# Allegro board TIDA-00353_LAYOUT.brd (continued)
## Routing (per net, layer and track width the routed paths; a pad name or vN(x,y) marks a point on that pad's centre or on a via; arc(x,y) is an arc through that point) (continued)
FMC_ADC_DEVCLK-: length 78.6
  L3_POWER w0.203: v1(119.61,87.25) 119.75,87.25 119.9,87.39 119.9,87.57 119.79,87.68 106.02,87.68 v1(105.92,87.58)
  BOTTOM w0.203: FMC.D9 v1(119.61,87.25) ; v1(105.92,87.58) 105.82,87.68 105.26,87.68 89.13,71.55 68.31,71.55 64.17,67.42 64.17,64.17 61.17,61.17 61.17,56.13 R77.1
FMC_ADC_SYSREF+: length 79.7
  L3_POWER w0.203: v1(119.61,84.71) 119.18,84.28 106.02,84.28 v1(105.92,84.38)
  BOTTOM w0.203: v1(105.92,84.38) 105.82,84.28 103.94,84.28 99.2,79.54 99.2,78.26 99.77,77.69 102.34,77.69 102.54,77.5 102.54,76.6 102.34,76.4 98.15,76.4 89.02,67.27 69.08,67.27 63.77,61.96 63.77,56.85 R83.1 ; FMC.D11 v1(119.61,84.71)
FMC_ADC_SYSREF-: length 79.7
  L3_POWER w0.203: v1(105.92,83.77) 106.02,83.87 119.75,83.87 119.9,83.73 119.9,83.54 119.79,83.44 v1(119.61,83.44)
  BOTTOM w0.203: FMC.D12 v1(119.61,83.44) ; v1(105.92,83.77) 105.82,83.87 104.11,83.87 99.61,79.37 99.61,78.43 99.94,78.1 102.51,78.1 102.95,77.67 102.95,76.43 102.51,76 98.32,76 89.19,66.87 69.25,66.87 64.17,61.79 64.17,56.85 R82.1
FMC_FPGA_DEVCLKA+: length 86.3
  TOP w0.203: U13.51 86.15,49.82 86.11,49.85 86.11,50.62 87.11,51.63 87.11,56.31 104.52,73.71 124.76,73.71 130.31,79.26 130.31,91.41 126.64,95.07 120.3,95.07 119.72,94.49 119.72,93.7 v1(119.61,93.6)
  BOTTOM w0.203: FMC.D4 v1(119.61,93.6)
FMC_FPGA_DEVCLKA-: length 86.3
  TOP w0.203: v1(120.88,93.6) 120.88,93.37 120.68,93.17 120.3,93.17 120.12,93.34 120.12,94.32 120.47,94.67 126.47,94.67 129.9,91.24 129.9,79.43 124.59,74.12 104.35,74.12 86.71,56.48 86.71,51.79 85.7,50.79 85.7,49.85 85.67,49.82 U13.52
  BOTTOM w0.203: FMC.D5 v1(120.88,93.6)
FMC_FPGA_DEVCLKB+: length 86.3
  TOP w0.203: v1(115.8,92.33) 126.55,92.33 128.28,90.6 128.28,80.04 124.48,76.25 103.54,76.25 83.74,56.45 83.74,55.47 84.61,54.6 84.61,49.85 84.65,49.82 U13.54
  BOTTOM w0.203: FMC.G6 v1(115.8,92.33)
FMC_FPGA_DEVCLKB-: length 86.3
  TOP w0.203: v1(115.8,91.06) 115.8,91.57 116.16,91.92 126.38,91.92 127.87,90.43 127.87,80.21 124.31,76.66 103.37,76.66 83.33,56.62 83.33,55.31 84.21,54.43 84.21,49.85 84.17,49.82 U13.55
  BOTTOM w0.203: FMC.G7 v1(115.8,91.06)
FMC_FPGA_SYSREF+: length 86.3
  TOP w0.203: v1(117.07,87.25) 116.78,87.25 116.65,87.12 116.65,86.87 116.96,86.56 119.94,86.56 121.16,87.78 126.19,87.78 126.73,87.25 126.73,80.65 124.86,78.79 103.6,78.79 82.19,57.38 82.19,55.34 81.62,54.77 79.83,54.77 79.63,54.57 79.63,53.67 79.83,53.48 82.06,53.48 82.63,52.91 82.63,51.77 83.61,50.79 83.61,49.85 83.66,49.8 U13.56
  BOTTOM w0.203: FMC.G9 v1(117.07,87.25)
FMC_FPGA_SYSREF-: length 86.3
  TOP w0.203: U13.57 83.15,49.8 83.2,49.85 83.2,50.62 82.22,51.6 82.22,52.74 81.89,53.07 79.66,53.07 79.22,53.51 79.22,54.74 79.66,55.17 81.45,55.17 81.78,55.5 81.78,57.54 103.43,79.2 124.69,79.2 126.32,80.82 126.32,87.08 126.02,87.38 121.33,87.38 120.11,86.16 116.79,86.16 116.25,86.7 116.25,87.06 116.06,87.25 v1(115.8,87.25)
  BOTTOM w0.203: FMC.G10 v1(115.8,87.25)
INA+: length 27.3
  TOP w0.203: T2.1 30.16,86.35 31.23,85.28 37.28,85.28 47.66,74.89 49.71,74.89 R8.2
INA-: length 27.3
  TOP w0.203: T2.3 30.16,83.81 31.23,84.88 37.11,84.88 47.5,74.49 49.6,74.49 R9.2
INB+: length 27.3
  TOP w0.203: T6.3 30.16,57.04 31.23,58.11 37.28,58.11 47.66,68.49 49.63,68.49 R21.2
INB-: length 27.3
  TOP w0.203: T6.1 30.16,59.58 31.23,58.51 37.11,58.51 47.5,68.9 49.66,68.9 R20.2
LMH_VINA:
  vias: v1(12.29,87.51)
LMH_VINB:
  vias: v1(12.29,55.88)
LMK_ADC_DEVCLK+: length 0.7
  BOTTOM w0.203: R74.1 C172.2
LMK_ADC_DEVCLK-: length 0.7
  BOTTOM w0.203: C173.2 R75.1
LMK_ADC_SYSREF+: length 0.7
  BOTTOM w0.203: R81.1 C170.2
LMK_ADC_SYSREF-: length 0.7
  BOTTOM w0.203: C171.2 R80.1
LMK_DIR: length 1.7
  BOTTOM w0.203: U16.7 54.69,19.78 55.42,19.05 R144.2
LMK_VCC1/5/6: length 5.3
  TOP w0.203: v2(78.38,44.46) 78.49,44.36 U13.10
  TOP w0.254: v1(88.38,42.86) U13.36 ; U13.33 88.35,41.36 v2(88.38,41.33)
  BOTTOM w0.381: v2(78.38,44.46) C131.1 C130.1 78.86,45.68 L20.1 ; v2(88.38,41.33) C132.1 ; v1(88.38,42.86) C133.1
LMK_VCC2: length 1.9
  TOP w0.203: U13.17 79.65,40.2 v2(79.55,40.09)
  BOTTOM w0.381: C141.1 v2(79.55,40.09)
  BOTTOM w0.559: L24.2 79.63,40.01 v2(79.55,40.09)
LMK_VCC3: length 2.1
  TOP w0.203: U13.21 81.65,40.2 v2(81.75,40.09)
  BOTTOM w0.381: C142.1 v2(81.75,40.09)
  BOTTOM w0.559: L25.2 81.18,39.52 v2(81.75,40.09)
LMK_VCC4: length 2.4
  TOP w0.254: v2(84.19,40.15) 84.17,40.17 U13.26
  BOTTOM w0.381: v2(84.19,40.15) C143.1
  BOTTOM w0.559: L26.2 84.43,40.39 v2(84.19,40.15)
LMK_VCC7: length 2
  TOP w0.254: U13.39 v1(88.38,44.36)
  BOTTOM w0.381: C136.1 v1(88.38,44.36) 89.21,44.36 L22.2
LMK_VCC8/10: length 9.3
  TOP w0.254: U13.47 v1(88.38,48.37) ; U13.42 v1(88.38,45.88)
  L4_POWER w0.559: v1(88.38,45.88) 89.08,46.58 89.08,47.66 v1(88.38,48.37)
  BOTTOM w0.381: C138.1 C140.1 v1(88.38,45.88) 89.21,45.88 L22.1 ; L21.1 88.38,49.51 v1(88.38,48.37) ; C139.1 v1(88.38,48.37) ; v1(88.38,48.37) 89.06,48.37 L23.1
LMK_VCC9: length 2
  TOP w0.203: v1(88.38,47.35) 88.35,47.38 U13.45
  BOTTOM w0.381: L23.2 89.06,47.35 v1(88.38,47.35) C137.1
LMK_VCC11: length 1.8
  TOP w0.254: v1(85.16,50.01) U13.53
  BOTTOM w0.381: C144.1 v1(85.16,50.01) 85.81,50.66 L27.2
LMK_VCC12: length 2.4
  TOP w0.254: U13.64 v2(79.65,50.09)
  BOTTOM w0.381: v2(79.65,50.09) C145.1
  BOTTOM w0.559: v2(79.65,50.09) 78.49,50.09 L28.2
OVRA/TRIGRDY: length 48.3
  TOP w0.381: v2(105.64,71.37) 116.08,71.37 116.44,71.02 116.44,66.29 v1(115.8,65.66)
  L4_POWER w0.381: v2(81.64,87.88) 83.16,86.36 90.66,86.36 v2(105.64,71.37)
  BOTTOM w0.381: FMC.G27 v1(115.8,65.66)
OVRB/TRIGGER: length 47.6
  TOP w0.381: v1(119.61,66.93) 118.98,66.29 118.98,65.38 118.62,65.02 105.47,65.02 v2(102.93,67.56)
  L4_POWER w0.381: v2(102.93,67.56) 87.3,83.19 v2(81.77,83.19)
  BOTTOM w0.381: FMC.D26 v1(119.61,66.93)
PG_C2M: length 13.9
  TOP w0.381: R60.1 108.51,100.2 116.69,100.2 117.58,99.31 118.98,99.31 v1(119.61,98.68)
  BOTTOM w0.381: FMC.D1 v1(119.61,98.68)
PG_M2C: length 10.6
  TOP w0.381: R61.1 116.44,99.31 v1(117.07,98.68)
  BOTTOM w0.381: FMC.F1 v1(117.07,98.68)
REFCLK+: length 5.8
  TOP w0.203: C166.2 83.02,35.71 80.87,33.55 T5.6
REFCLK-: length 5.8
  TOP w0.203: T5.4 85.95,33.55 83.79,35.71 C165.2
RESET_LMK_3P3: length 16.9
  TOP w0.203: v2(73.38,23.89) v2(73.38,22.62)
  BOTTOM w0.203: R153.1 R152.2 74.27,21.73 v2(73.38,22.62) ; v2(73.38,23.89) 73.38,32.91 R95.1
SA0+: length 53.9
  TOP w0.203: v1(124.69,96.14) 124.26,96.57 123.56,96.57 122.98,97.16 106.73,97.16 83.41,73.84 82.15,73.84 81.97,73.66 C101.1
  BOTTOM w0.203: FMC.A3 v1(124.69,96.14)
SA0-: length 53.9
  TOP w0.203: C100.1 81.97,74.42 82.15,74.24 83.24,74.24 106.56,97.56 123.14,97.56 123.73,96.98 124.26,96.98 v1(124.69,97.41)
  BOTTOM w0.203: FMC.A2 v1(124.69,97.41)
SA1+: length 47.9
  TOP w0.203: C103.1 81.97,71.37 82.15,71.55 83.79,71.55 102.46,90.22 120.45,90.22 v1(120.88,89.79)
  BOTTOM w0.203: FMC.C7 v1(120.88,89.79)
SA1-: length 47.9
  TOP w0.203: C102.1 81.97,72.14 82.15,71.96 83.62,71.96 102.29,90.63 120.45,90.63 v1(120.88,91.06)
  BOTTOM w0.203: FMC.C6 v1(120.88,91.06)
SA_0+: length 14.9
  TOP w0.203: C101.2 80.93,73.66 80.75,73.84 71.6,73.84 70.75,72.99 67.46,72.99 67.42,72.94 U12.38
SA_0-: length 14.9
  TOP w0.203: U12.39 67.42,73.44 67.46,73.4 70.58,73.4 71.43,74.24 80.7,74.24 80.88,74.42 C100.2
SA_1+: length 14.8
  TOP w0.203: U12.36 67.42,71.94 67.46,71.99 74.23,71.99 74.67,71.55 80.83,71.55 81.01,71.37 C103.2
SA_1-: length 14.8
  TOP w0.203: U12.37 67.42,72.44 67.46,72.4 74.39,72.4 74.83,71.96 80.88,71.96 81.06,72.14 C102.2
SB0+: length 51.5
  TOP w0.203: v1(124.69,84.71) 124.26,85.14 102.71,85.14 84.55,66.98 82.15,66.98 81.97,66.8 C107.1
  BOTTOM w0.203: FMC.A11 v1(124.69,84.71)
SB0-: length 51.5
  TOP w0.203: C106.1 81.97,67.56 82.15,67.39 84.38,67.39 102.54,85.55 124.26,85.55 v1(124.69,85.98)
  BOTTOM w0.203: FMC.A10 v1(124.69,85.98)
SB1+: length 52.7
  TOP w0.203: C105.1 82.1,69.09 82.28,69.27 84.17,69.27 103.86,88.95 122.5,88.95 123.77,90.22 124.26,90.22 v1(124.69,89.79)
  BOTTOM w0.203: FMC.A7 v1(124.69,89.79)
SB1-: length 52.7
  TOP w0.203: C104.1 82.1,69.85 82.28,69.67 84,69.67 103.69,89.36 122.33,89.36 123.6,90.63 124.26,90.63 v1(124.69,91.06)
  BOTTOM w0.203: FMC.A6 v1(124.69,91.06)
SB_0+: length 15.8
  TOP w0.203: U12.32 67.42,69.94 67.46,69.99 71.72,69.99 74.73,66.98 80.83,66.98 81.01,66.8 C107.2
SB_0-: length 15.8
  TOP w0.203: C106.2 81.01,67.56 80.83,67.39 74.9,67.39 71.89,70.4 67.46,70.4 67.42,70.44 U12.33
SB_1+: length 15.3
  TOP w0.203: U12.34 67.42,70.94 67.46,70.99 72.58,70.99 74.31,69.27 80.75,69.27 80.93,69.09 C105.2
SB_1-: length 15.3
  TOP w0.203: U12.35 67.42,71.44 67.46,71.4 72.75,71.4 74.48,69.67 80.7,69.67 80.88,69.85 C104.2
SCLK_ADC_3P0: length 31.7
  TOP w0.203: v2(61.19,93.47) 62.04,92.62 62.04,80.43 v2(61.63,80.01) ; U12.53 61.22,76.68 v1(61.19,76.71)
  BOTTOM w0.203: R134.2 v2(61.19,93.47) J3.1 R65.2 ; v2(61.63,80.01) 61.63,77.14 v1(61.19,76.71)
SCLK_ADC_LMH_LMK: length 44.3
  TOP w0.203: v2(28.35,24.77) 37.9,24.77 38.41,24.26 40.28,24.26 40.79,24.77 v2(45.97,24.77) v2(45.97,28.83)
  BOTTOM w0.203: v2(45.97,24.77) 45.97,22.91 46.5,22.38 U16.14 ; R126.2 v2(28.35,24.77) 22.63,24.77 21.13,26.27 U15.14 ; U14.14 v2(45.97,28.83)
SCLK_LMH_3P3: length 40.9
  L4_POWER w0.203: J1.1 14.16,50.72 8.86,56.02 8.86,69.02 10.08,70.25 v2(10.15,70.25)
  BOTTOM w0.203: R138.2 19.24,41.28 J1.1
  BOTTOM w0.254: U3.2 10.35,70.44 v2(10.15,70.25)
SCLK_LMK_3P3: length 47.8
  TOP w0.203: U13.19 80.66,39.41 78.36,37.11 78.36,22.13 76.95,20.72 v2(75.54,20.72)
  BOTTOM w0.203: R150.1 R151.1 v2(75.54,20.72) 75.54,21.89 74.18,23.26 61.36,23.26 J2.1 58.02,24.27 R141.2
SDI_ADC_3P0: length 28
  TOP w0.203: v2(63.23,90.42) 64.75,88.9 v2(64.75,80.01) ; U12.47 64.22,76.8 v1(64.17,76.86)
  BOTTOM w0.203: R136.2 v2(63.23,90.42) J3.3 R63.1 ; v1(64.17,76.86) 64.37,77.06 64.37,79.63 v2(64.75,80.01)
SDI_ADC_LMH: length 37.9
  TOP w0.203: v2(31.41,25.65) v2(31.41,27.53)
  BOTTOM w0.203: U15.12 22.43,29.11 24,27.53 v2(31.41,27.53) 34.95,27.53 37.01,25.48 37.01,24.54 37.74,23.8 41.45,23.8 45.19,27.53 U14.12 ; v2(31.41,25.65) v1(31.41,21.93)
SDI_LMH_3P3: length 44.6
  L4_POWER w0.203: v2(10.97,69.76) 10.08,68.88 10.08,64.16 12.85,61.39 12.85,53.93 14.79,51.99 19.87,51.99 20.51,51.35 20.51,50.08 21.14,49.45 23.05,49.45 J1.3
  BOTTOM w0.203: R140.2 24.32,41.28 J1.3
  BOTTOM w0.254: U3.1 11.15,69.94 v2(10.97,69.76)
SDIO_LMK: length 14.2
  TOP w0.203: v1(34.43,21.93) 34.43,21.65 35,21.08 v2(46.79,21.08)
  BOTTOM w0.203: U16.12 v2(46.79,21.08)
SDIO_LMK_3P3: length 48.9
  TOP w0.203: U13.20 81.15,39.13 79,36.99 79,21.85 77.23,20.08 v2(70.71,20.08) v2(67.03,20.08)
  BOTTOM w0.203: J2.3 58.02,19.19 R143.2 ; J2.3 61.23,20.08 v2(67.03,20.08) ; J2.3 J2.4 ; v2(70.71,20.08) R149.1 R148.1
SDO_ADC: length 25
  TOP w0.203: v2(33.67,25.65) v2(33.67,26.88)
  BOTTOM w0.203: v2(33.67,26.88) 34.75,26.88 36.25,25.39 36.25,23.47 38.2,21.51 40.08,21.51 42.91,24.34 42.91,24.37 45.42,26.88 U14.11 ; v2(33.67,25.65) v1(33.67,21.93)
SDO_ADC_3P0: length 25.3
  TOP w0.203: U12.48 v1(63.72,76.44) ; v2(63.35,88.9) v2(63.35,80.01)
  BOTTOM w0.203: v1(63.72,76.44) 63.35,76.81 v2(63.35,80.01) ; R64.1 J3.4 64.24,88.9 v2(63.35,88.9) R137.2
SYNC_LMK_3P3: length 25.6
  TOP w0.203: v2(76.71,35.92) 76.71,22.31 76.39,21.99 v2(68.94,21.99)
  BOTTOM w0.203: R155.1 R156.2 v2(68.94,21.99)
SYNCB+: length 75
  TOP w0.203: U12.27 65.72,67.31 65.77,67.26 65.77,66.67 66.5,65.94 66.5,59.27 70.17,55.6 77.92,55.6 102.38,80.06 116.05,80.06 116.64,80.65 116.64,83.01 117,83.36 v1(117.07,83.44)
  BOTTOM w0.203: FMC.G12 v1(117.07,83.44)
SYNCB-: length 75
  TOP w0.203: U12.28 66.22,67.31 66.17,67.26 66.17,66.84 66.91,66.11 66.91,59.44 70.34,56.01 77.75,56.01 102.21,80.47 115.88,80.47 116.24,80.82 116.24,82.83 116.11,82.96 115.27,82.96 115.13,83.1 115.13,83.27 115.3,83.44 v1(115.8,83.44)
  BOTTOM w0.203: FMC.G13 v1(115.8,83.44)
SYSREF+: length 4.2
  TOP w0.203: U12.23 63.72,67.28 63.77,67.24 63.77,64.15 63.6,63.98 C110.2
SYSREF-: length 4.2
  TOP w0.203: U12.24 64.22,67.28 64.17,67.24 64.17,64.15 64.35,63.98 C111.2
SYSREF_VIN+: length 9.1
  TOP w0.203: C110.1 63.6,62.5 R50.2 63.77,62.33 63.77,55.17 v1(63.46,54.86)
  BOTTOM w0.203: v1(63.46,54.86) R83.2
SYSREF_VIN-: length 9.1
  TOP w0.203: C111.1 64.35,62.5 R50.1 64.17,62.33 64.17,55.17 v1(64.48,54.86)
  BOTTOM w0.203: v1(64.48,54.86) R82.2
V_VCXO3.3: length 83.9
  TOP w0.559: V_VCXO3P3.1 Z13.3 v2(102.44,28.97) ; v2(97.03,57.62) C169.1 98.68,57.62 ; 98.68,57.62 100.67,57.62 ; 98.68,57.62 v2(98.68,58.15) v2(100.67,58.15) 100.67,57.62 ; 98.68,57.62 v2(98.68,57.09) v2(100.67,57.09) 100.67,57.62
  TOP w0.762: v2(100.51,51.32) v2(100.51,52.64)
  L3_POWER w0.559: 100.67,57.62 v2(100.67,57.09) v2(98.68,57.09) 98.68,57.62 ; 100.67,57.62 98.68,57.62 ; 100.67,57.62 v2(100.67,58.15) v2(98.68,58.15) 98.68,57.62 ; 98.68,57.62 v2(97.03,57.62)
  L3_POWER w1.27: V_VCXO3P3.1 104.86,52.44 100.67,56.63 100.67,57.62
  BOTTOM w0.762: 98.68,53.17 98.68,52.64 v2(100.51,52.64) ; 98.68,53.17 98.68,53.71 100.67,53.71 100.67,52.64 v2(100.51,52.64) ; 98.68,53.17 100.51,53.17 ; 100.67,57.62 v2(100.67,57.09) v2(98.68,57.09) v2(98.68,58.15) v2(100.67,58.15) 100.67,57.62 ; 100.67,57.62 100.51,57.62 ; v2(100.51,52.64) v2(100.51,51.32) Y3.6 ; v2(100.51,52.64) 100.51,53.17 ; 100.51,57.62 100.51,53.17 ; 100.51,57.62 v2(97.03,57.62)
  BOTTOM w1.27: Z13.3 V_VCXO3P3.1
  vias: v2(104.35,29.33) v2(104.35,28.62) v2(105.36,29.33) v2(105.36,28.62)
V_XO3.3: length 36.3
  TOP w0.559: 97.07,35.74 v2(97.47,35.74) v2(97.47,33.67) ; 97.07,35.74 Y1.6 ; 97.07,35.74 v2(96.66,35.74) v2(96.66,33.67) ; v2(97.47,33.67) Y1.6 ; v2(97.47,33.67) v2(97.47,31.6) 97.07,31.6 ; Y1.6 97.07,31.6 ; Y1.6 v2(96.66,33.67) ; v2(93.64,17.85) Z12.3 ; v2(96.66,33.67) v2(96.66,31.6) 97.07,31.6
  TOP w1.016: v2(96.66,31.6) 96.05,30.99 v1(96.05,22.9) V_XO3P3.1 Z12.3
  BOTTOM w0.381: v1(96.05,22.9) V_XO3P3.1
  BOTTOM w1.27: Z12.3 V_XO3P3.1
  vias: v2(95.54,18.2) v2(95.54,17.5) v2(96.56,18.2) v2(96.56,17.5)
VA1.2: length 194.7
  TOP w0.203: v2(58.6,54.04) 57.82,53.26 SYSREF_SW.1 ; C85.1 63.1,65.76 62.72,66.14 U12.21
  TOP w0.305: U12.30 67.71,68.94 68.05,68.61 C93.1 ; C74.2 56.75,71.25 56.95,71.44 U12.8 ; C65.1 62.87,77.16 62.72,77.01 U12.50
  TOP w0.381: C65.1 62.87,77.83 v1(62.84,77.85) C64.1 v1(62.84,79.12) ; C74.2 56.39,70.97 v1(55.99,71.37) ; v1(68.97,68.58) 68.48,68.58 C93.1 ; C85.1 v1(63.15,65.34)
  TOP w0.406: v1(68.97,68.58) 69.16,68.58 v1(69.53,68.95) C92.1
  TOP w0.559: 53.79,100.85 C207.1 ; v2(56.53,100.49) v2(56.53,101.2) v2(55.52,101.2) v2(54.5,101.2) v2(54.5,100.49) v2(55.52,100.49) v2(56.53,100.49)
  TOP w1.27: VA1P2.1 52.04,97.55 C206.1 Z4.3
  L3_POWER w0.203: v2(58.6,54.04) 63.94,59.38 63.94,64.55 v1(63.15,65.34)
  L4_POWER w0.635: v1(68.97,68.58) 69.16,68.58 v1(69.53,68.95) 69.98,69.39 69.98,73.33 67.67,75.64 67.67,83.31 69.39,85.03 69.39,101.22 65.86,104.75 58.8,104.75 58.06,104.01 58.06,102.01 57.26,101.2 v2(56.53,101.2) v2(56.53,100.49) ; v2(54.5,101.2) v2(54.5,100.49) 54.5,98.51 54.84,98.17 54.84,87.99 58.53,84.3 58.53,76.96 59.29,76.2 59.29,68.5 59.97,67.82 62.08,67.82 62.46,67.44 62.46,66.03 v1(63.15,65.34) ; v1(62.84,77.85) v1(62.84,79.12) 62.84,79.37 62.46,79.75 62.46,83.41 57.79,88.09 57.79,97.5 55.52,99.77 v2(55.52,100.49) v2(55.52,101.2) ; VA1P2.1 52.05,95.89 53.07,94.87 53.07,85.34 51.29,83.57 51.29,76.65 52.78,75.16 52.78,75.13 52.92,74.99 52.92,74.39 52.78,74.24 52.78,74.19 55.6,71.37 v1(55.99,71.37)
  BOTTOM w0.381: C76.2 56.6,71.37 v1(55.99,71.37) 56.14,71.53 C75.2 ; C91.1 v1(68.97,68.58) ; v1(63.15,65.34) 62.86,65.63 C84.1
VA1.8: length 338.3
  TOP w0.203: U12.20 62.22,66.14 61.84,65.76 C80.1
  TOP w0.254: v1(59.72,65.56) 59.66,65.61 59.66,67.06 59.72,67.11 U12.15
  TOP w0.284: U12.56 59.72,77.32
  TOP w0.305: U12.29 67.45,68.44 67.69,68.2 67.69,67.82 v1(67.7,67.82) ; 59.72,77.32 C67.1 ; U12.7 56.94,71.94 56.75,72.14 C73.2 ; U12.51 62.22,77.31 C69.1
  TOP w0.33: C82.1 v1(59.72,65.56)
  TOP w0.381: C69.1 v1(62.18,77.88) 62.2,77.88 C68.1 62.21,78.99 v1(62.08,79.12) ; C90.2 v1(68.33,67.82) v1(67.7,67.82) ; v1(59.42,79.12) C66.1 59.42,77.88 v1(59.47,77.83) 59.7,77.6 C67.1 ; C80.1 v1(61.8,65.34) ; C73.2 56.72,72.39 56.22,72.39 v1(55.99,72.16)
  TOP w0.762: Z7.3 C217.1
  TOP w1.27: VA1P8.1 Z7.3
  L3_POWER w0.635: 45.06,32 v2(44.68,32) v2(44.68,32.77) 45.06,32.77 ; 45.06,32 45.06,32.77 ; 45.06,32 v2(45.45,32) v2(45.45,32.77) ; v2(45.45,32.77) 45.45,35.38 46.51,36.45 46.51,38.33 50.65,42.47 50.65,66.05 55.17,70.56 55.17,71.73 55.6,72.16 v1(55.99,72.16) ; v2(45.45,32.77) 45.06,32.77 ; v1(59.42,79.12) 59.42,77.88 v1(59.47,77.83) 59.47,76.89 57.38,74.8 57.38,69.16 58.43,68.12 58.43,64.34 57.73,63.65 57.73,57.3 51.99,51.56 51.99,40.08 50.91,38.99 50.91,35.69 48.37,33.15 VA1P8.1 49.63,32.38 52.18,34.93 52.18,38.71 53.34,39.88 53.34,50.47 58.13,55.26 58.13,55.47 58.56,55.89 58.81,55.89 60.93,58.01 60.93,67.16 60.03,68.06 59.8,68.06 58.83,69.03 58.83,69.26 58.83,74.6 59.95,75.72 61.96,75.72 62.51,76.28 62.51,76.89 62.18,77.22 v1(62.18,77.88) 62.08,77.98 v1(62.08,79.12)
  L4_POWER w0.635: VA1P8.1 48.37,33.45 46.23,35.59 46.23,40.28 46.53,40.59 46.53,50.24 48.42,52.12 51.97,52.12 62.48,62.64 64.52,62.64 68.33,66.45 v1(68.33,67.82) v1(67.7,67.82) ; v1(61.8,65.34) 61.8,65.18 49.99,53.37 42.47,53.37 41.13,52.02 41.13,36.21 44.57,32.77 v2(44.68,32.77) v2(45.45,32.77) ; v2(45.45,32) v2(44.68,32) 43.62,30.94 41.33,30.94 39.81,32.46 39.81,52.45 42.47,55.12 49.63,55.12 57.51,62.99 57.51,63.35 v1(59.72,65.56)
  BOTTOM w0.203: C89.2 67.54,67.82 v1(67.7,67.82) v1(68.33,67.82)
  BOTTOM w0.33: C79.1 59.84,65.43 v1(59.72,65.56)
  BOTTOM w0.381: C72.2 56.57,72.39 56.22,72.39 v1(55.99,72.16) ; C81.1 61.52,65.63 v1(61.8,65.34)
  BOTTOM w1.27: Z7.3 VA1P8.1
VA3.0: length 202.8
  TOP w0.295: U12.42 67.46,74.94
  TOP w0.305: U12.2 58.25,74.44 58.09,74.6 57.05,74.6 56.75,74.3 C71.1 ; C94.2 67.7,75.18 67.46,74.94 ; C77.2 56.65,68.96 56.77,68.83 58.14,68.83 58.25,68.94 U12.13
  TOP w0.381: C77.2 56.14,69.34 v1(55.89,69.09) ; v1(55.99,74.3) 56.24,74.04 C71.1 ; C94.2 v1(68.71,75.79)
  TOP w0.762: C226.1 Z9.3
  TOP w1.27: Z9.3 VA3.0.1
  L4_POWER w0.635: 72.37,76.2 79.83,83.66 79.83,92.2 84.59,96.96 84.59,100.71 83.85,101.44 v2(83.29,101.44) ; 72.37,76.2 74.22,74.35 74.22,66.04 67.59,59.41 65.43,59.41 62.43,56.41 58.65,56.41 55.8,53.57 55.8,52.25 53.94,50.38 49.2,50.38 48.78,49.96 v2(48.56,49.96) v2(47.85,49.96) ; 72.37,76.2 69.12,76.2 v1(68.71,75.79) ; v1(55.89,69.09) 53.59,69.09 52.92,68.42 52.92,68.39 52.5,67.97 52.47,67.97 51.61,67.11 51.61,65.68 47.65,61.72 35.28,61.72 29.11,55.55 29.11,50.85 26.72,48.46 26.72,43.79 27.89,42.62 29.27,42.62 v2(30.49,41.4) ; v1(55.99,74.3) 57.13,73.15 57.13,69.04 56.38,68.29 55.74,68.29 55.31,67.86 55.31,66.78 48.55,60.01 37.25,60.01 34.67,57.43 34.67,46.81 33.15,45.29 v2(33.15,41.35) v2(32.44,41.35)
  BOTTOM w0.381: C70.1 56.24,74.04 v1(55.99,74.3) ; v1(68.71,75.79) 68.56,75.64 C95.2
  BOTTOM w0.406: C78.2 56.14,69.34 v1(55.89,69.09)
  BOTTOM w1.27: Z9.3 VA3.0.1
  vias: v2(31.2,41.4) v2(32.83,40.69) v2(44.68,43.31) v2(44.68,42.44) v2(45.54,43.3) v2(45.53,42.44)
VA3.0_LED: length 137.5
  TOP w0.762: C228.1 Z14.3
  TOP w1.27: Z14.3 VA3.0_LED.1
  L4_POWER w0.508: JP1.1 43.83,27.84 45.18,29.19 45.18,29.49 46.84,31.14 ; 46.84,31.14 47.78,30.2 48.82,30.2 v2(54.11,24.92) ; 46.84,31.14 46.58,31.39 46.58,33.27 43.92,35.94 43.92,43.97 44.68,44.73 v2(44.68,47.24)
  L4_POWER w0.635: v2(101.83,64.52) 101.38,64.97 76.28,64.97 ; 76.28,64.97 76.28,76.05 80.62,80.39 v2(87.86,80.39) ; 76.28,64.97 76.28,63.59 74.49,61.8 74.49,60.5 68.22,54.23 66.76,54.23 61.55,49.02 60.25,49.02 59.33,48.11 48.64,48.11 VA3.0_LED.1
  BOTTOM w0.203: v2(54.11,24.92) U14.8
  BOTTOM w0.381: v2(87.86,85.09) v2(87.86,80.39)
  BOTTOM w1.27: Z14.3 VA3.0_LED.1
  vias: v2(44.68,48.13) v2(45.57,48.13) v2(45.57,47.24)
VADJ: length 75.7
  TOP w0.508: v2(105.14,99.31) R61.2 ; v1(119.61,49.15) v1(118.34,49.15) v1(117.07,49.15) v1(115.8,49.15) 113.16,46.51 v2(110.65,46.51) 107.55,46.51 106.41,47.65 R69.1
  BOTTOM w0.381: FMC.H40 v1(115.8,49.15) ; FMC.F40 v1(118.34,49.15) ; FMC.E39 v1(119.61,49.15) ; FMC.G39 v1(117.07,49.15)
  BOTTOM w0.635: v2(105.14,99.31) 110.65,93.8 v2(110.65,46.51)
VAMP: length 15.3
  BOTTOM w0.203: v2(15.17,68.04) 14.99,68.22 U3.27 ; U3.14 14.99,75.17 v2(15.17,75.35)
  BOTTOM w0.381: v2(15.17,67.15) C24.2 ; C26.2 v2(15.17,76.24) ; v2(15.17,68.04) C25.1 ; v2(15.17,75.35) C27.1
  BOTTOM w0.406: R30.2 v1(8.53,69.83) ; 15.41,76.24 15.41,75.35 ; C24.2 C25.1 ; C26.2 C27.1 ; v2(15.17,67.15) v2(15.17,68.04) ; R33.2 v1(8.53,73.56) ; v2(15.17,76.24) v2(15.17,75.35) ; 15.41,67.15 15.41,68.04
  BOTTOM w0.762: v2(7.65,49.7) 10.22,49.7 Z17.3 v2(10.16,51.48)
  vias: v2(9.58,49.98) v2(9.58,49.28) v2(10.74,49.98) v2(10.74,49.28) v2(10.85,68.48)
VD1.2: length 78.9
  TOP w0.203: 62.24,100.85 62.24,101.02 C209.1
  TOP w0.254: U12.26 65.22,67.11 65.36,66.97 65.36,65.87 65.25,65.76 65.25,65.48
  TOP w0.305: C62.1 65.36,77.28 65.22,77.14 U12.45
  TOP w0.33: C88.1 65.25,65.48 v1(65.38,65.35)
  TOP w0.381: C62.1 65.64,77.62 v1(65.64,77.85) C61.1 v1(65.64,79.12)
  TOP w1.27: Z6.3 C208.1 59.66,97.67 VD1P2.1
  L4_POWER w0.635: v2(63.14,101.2) v2(63.14,100.49) 62.2,99.56 62.2,87.18 64.88,84.51 64.88,83.69 65.64,82.93 v1(65.64,79.12) v1(65.64,77.85) ; v1(65.38,65.35) 65.64,65.61 65.64,67.41 66.71,68.48 66.71,85.62 65.41,86.92 65.41,99.24 v2(64.15,100.49) v2(64.15,101.2)
  BOTTOM w0.33: C87.1 v1(65.38,65.35) 65.38,65.36 C86.2
VIO_B_M2C: length 8.1
  TOP w0.508: R69.2 108.77,48.39 109.28,47.88 v1(111.99,47.88) v1(113.26,49.15)
  BOTTOM w0.381: FMC.K40 v1(111.99,47.88) ; FMC.J39 v1(113.26,49.15)
VLMK3.3: length 119
  TOP w0.559: v2(57.76,45.87) v2(57.12,45.87) v2(56.49,45.87) 54.48,43.87 54.48,38.81 ; 18.88,42.57 35.43,42.57 39.19,38.81 54.48,38.81 ; 18.88,42.57 18.88,44.38 23.24,48.74 v1(25.84,48.74) ; 18.88,42.57 v1(18.88,31.36) ; 54.48,38.81 54.48,30.17 v1(48.94,24.63) ; v2(83.06,15.87) Z11.3 VLMK3P3.1
  L4_POWER w0.559: v2(71.91,45.87) v2(71.27,45.87) v2(70.64,45.87) v2(57.76,45.87) v2(57.12,45.87) v2(56.49,45.87)
  BOTTOM w0.203: v1(48.94,24.63) 48.94,24.05 48.57,23.68 U16.16 ; U15.16 v1(18.88,31.36)
  BOTTOM w0.381: C135.1 v2(76.64,48.79)
  BOTTOM w0.559: L28.1 78.36,48.69 L20.2
  BOTTOM w0.762: L21.2 v2(88.02,51.21) 87.76,51.21 v2(87.23,50.67) ; L28.1 v2(78.24,48.79) v2(76.64,48.79) ; v2(81.18,38) L24.1
  BOTTOM w1.27: Z11.3 VLMK3P3.1
  vias: v2(69.09,23.87) v2(75.7,23.87) v2(84.97,16.22) v2(84.97,15.51) v2(85.48,38.96) v2(85.98,16.22) v2(85.98,15.51)
VSPI1.8: length 52.9
  TOP w0.381: R123.2 v1(35.96,21.98) ; v2(30.59,20.43) 30.11,20.91 R122.2 R124.2
  TOP w0.559: Z3.3 v2(17.33,12.62)
  TOP w1.27: VSPI1.8.1 Z3.3
  L4_POWER w0.559: v1(20.26,30) 18.79,28.52 18.79,16.52 VSPI1.8.1 ; v2(42.22,21.98) v2(41.66,21.98) ; v2(42.22,21.98) v2(42.78,21.98) 45.47,21.98 v1(46.74,23.25) ; v2(42.22,21.98) 42.22,24.08 46.08,27.94 46.4,27.94 46.91,28.45 v2(46.91,29.42) ; v2(41.66,14.05) v2(42.22,14.05) v2(42.78,14.05) 49.18,14.05 JP2.1
  BOTTOM w0.203: v1(20.26,30) 20.48,30.21 U15.15 ; U16.15 46.95,23.03 v1(46.74,23.25) ; U14.15 46.98,29.48 v2(46.91,29.42)
  BOTTOM w0.381: C184.1 30.59,20.86 v2(30.59,20.43) U6.4
  BOTTOM w0.508: v2(46.91,29.42) 46.53,29.42 46.45,29.49 C190.2
  vias: v2(19.23,12.97) v2(19.23,12.26) v2(20.25,12.97) v2(20.25,12.26)
N17161280: length 19.6
  TOP w0.508: 33.72,46.6 C224.1 35.32,46.78 R170.2 ; 33.72,46.6 U10.5 ; 33.72,46.6 C223.1
  TOP w0.762: R179.1 Z14.1
  TOP w1.27: 40.28,44.93 Z9.1 ; 40.28,44.93 C223.1 ; 40.28,44.93 Z14.1
N17161345: length 4
  TOP w0.254: C224.2 35.32,48.05 R170.1 R171.1
  TOP w0.508: C224.2 U10.6
N17161357: length 1.2
  TOP w0.254: C222.1 U10.1
N17161563: length 64.3
  TOP w0.508: 100.49,13.02 U11.5 ; 100.49,13.02 C233.1 100.62,11.6 100.62,10.22 R177.2 ; 100.49,13.02 C234.1
  TOP w0.762: R180.1 Z12.1
  TOP w1.27: Z12.1 C234.1
  L4_POWER w0.559: 105.36,24.15 v2(105.36,23.79) v2(104.35,23.79) 104.35,24.15 ; 105.36,24.15 v2(105.36,24.5) v2(104.35,24.5) 104.35,24.15 ; 105.36,24.15 104.35,24.15 ; 95.54,13.02 v2(95.54,12.67) v2(96.56,12.67) v2(96.56,13.38) v2(95.54,13.38) 95.54,13.02 ; 95.54,13.02 Z12.1
  L4_POWER w1.27: Z12.1 99.58,13.02 100.08,12.52 105.19,12.52 106.48,13.82 106.48,22.52 105.36,23.64 105.36,24.15
  BOTTOM w0.559: 96.56,13.02 v2(96.56,13.38) v2(95.54,13.38) v2(95.54,12.67) v2(96.56,12.67) 96.56,13.02 ; 96.56,13.02 Z12.1 ; 105.36,24.15 v2(105.36,23.79) v2(104.35,23.79) 104.35,24.15 ; 105.36,24.15 104.35,24.15 ; 105.36,24.15 v2(105.36,24.5) v2(104.35,24.5) 104.35,24.15 ; 84.97,11.04 v2(84.97,11.39) v2(85.98,11.39) v2(85.98,10.69) v2(84.97,10.69) 84.97,11.04 ; 84.97,11.04 85.4,11.04
  BOTTOM w1.27: 85.4,11.04 91.3,11.04 93.29,13.02 Z12.1
N17161629: length 2.7
  TOP w0.203: R176.1 R175.2
  TOP w0.254: R175.2 U11.8
N17161669: length 4.1
  TOP w0.254: R178.1 R177.1 101.94,11.6 C233.2
  TOP w0.508: C233.2 U11.6
N17161679: length 1.2
  TOP w0.305: U11.1 v2(103.71,18.01)
N17161879: length 23.9
  TOP w0.508: 75.41,100.14 U8.5 ; 75.41,100.14 v2(75.41,98.72) ; 75.41,100.14 C204.1
  TOP w1.27: C204.1 73.11,100.14 71.12,102.13 68.99,102.13 65.45,105.67 Z6.1 Z4.1
N17161936: length 4.7
  TOP w0.406: U8.8 80.46,100.14 R235.2 81.5,100.15 C200.2 R161.2 R160.2
N17162041: length 11.7
  TOP w0.508: R166.2 35.7,33.7 C215.1 34.1,33.52 ; 34.1,33.52 U9.5 ; 34.1,33.52 C214.1
  TOP w1.27: Z7.1 38.84,32.38 38.3,31.85 C214.1
N17162051: length 4.8
  TOP w0.508: C210.2 R165.2 R164.2 ; C210.2 34.09,38.9 R236.2 ; C210.2 U9.8
N17162120: length 4
  TOP w0.254: C215.2 35.7,34.97 R166.1 R167.1
  TOP w0.508: U9.6 C215.2
N17162132: length 1.2
  TOP w0.254: U9.1 C213.1
N17162350: length 3
  TOP w0.254: v2(77.04,98.72) R162.1 R163.1
  TOP w0.508: U8.6 v2(77.04,98.72)
N17162360: length 1.2
  TOP w0.305: U8.1 C203.1
N17167261: length 1.7
  BOTTOM w0.203: LMKSPI.2 R147.2
N17167267: length 1.8
  BOTTOM w0.203: LMKSPI.4 70.71,16.08 R149.2
N17167273: length 1.7
  BOTTOM w0.203: R151.2 LMKSPI.8
N17204057: length 14.8
  BOTTOM w0.33: Y3.1 100.02,40.68 C162.1 88.69,38.21 R103.2
N17204061: length 2.6
  TOP w0.203: U13.32 87.17,39.74 C160.1 C161.1
  vias: v2(88.69,39.64)
N17204110: length 26.9
  TOP w0.33: REFCLK.1 79.12,3.87 80.87,5.62 T5.1
N17204122: length 1
  TOP w0.254: U13.12 v1(78.43,43.36)
  BOTTOM w0.381: C149.1 v1(78.43,43.36)
N17204150: length 2.3
  BOTTOM w0.203: Y1.4 91.99,35.24 v1(91.5,35.73)
N17204206: length 2.3
  TOP w0.203: U13.11 78.1,43.87 77.25,44.73 C148.1
N17204360: length 34.6
  TOP w0.33: R108.1 R107.2 89.65,6.04 91.82,3.87 EXTREF.1
N17204562: length 3.2
  TOP w0.203: C151.1 C150.1 89.12,47.86 U13.46
N17204592: length 1.4
  TOP w0.203: C150.2 R100.1
N17204632:
  vias: v1(94.92,46.23)
N17204638: length 1.7
  TOP w0.33: C158.2 R101.2 R102.1
N17204674: length 3.9
  BOTTOM w0.381: Y1.1 v1(97.07,23.79) R112.1
N17204744: length 1.8
  TOP w0.203: C152.1 89.29,46.82 88.14,46.82 88.09,46.87 U13.44
N17243114: length 85.7
  TOP w0.203: v1(109.4,53.59) 113.9,53.59 v1(114.53,52.96)
  BOTTOM w0.203: R65.1 74.4,93.22 105.69,93.22 109.4,89.51 v1(109.4,53.59) ; v1(114.53,52.96) FMC.H37
N17243121: length 87
  TOP w0.203: v1(108.59,51.05) 113.9,51.05 v1(114.53,50.42)
  BOTTOM w0.203: R66.1 73.26,91.82 105.92,91.82 108.59,89.15 v1(108.59,51.05)
  BOTTOM w0.381: FMC.H38 v1(114.53,50.42)
N17243521: length 83.2
  TOP w0.203: v1(115.8,54.23) 115.17,54.86 v1(107.78,54.86)
  BOTTOM w0.203: R63.2 72.24,90.3 106.28,90.3 107.78,88.8 v1(107.78,54.86) ; FMC.G36 v1(115.8,54.23)
N17243524: length 84.5
  TOP w0.203: v1(115.8,51.69) 115.17,52.32 v1(106.96,52.32)
  BOTTOM w0.203: v1(106.96,52.32) 106.96,88.44 106.51,88.9 71.1,88.9 R64.2 ; v1(115.8,51.69) FMC.G37
N17262131: length 21.5
  TOP w0.305: v1(67.8,74.55) 67.67,74.42 66.68,74.42 U12.41
  TOP w0.381: C96.1 68.18,74.42 68.05,74.55 v1(67.8,74.55)
  BOTTOM w0.381: C98.1 67.14,75.21 v1(67.8,74.55) 68.05,74.55 69.32,73.28 C97.2 74.4,73.28 75.04,73.91 80.6,73.91 81.77,75.08 BP2.5.1
N17267182: length 13
  TOP w0.203: v2(78.38,46.26) 78.49,46.36 U13.6 ; v2(75.7,35.92) v2(75.7,36.8)
  BOTTOM w0.203: v2(78.38,46.26) 77.78,45.66 77.78,38.89 v2(75.7,36.8) v2(75.7,35.92)
N17394464: length 2.1
  TOP w0.381: Q4.3 SYNC.2
  vias: v2(102.6,60.33)
N17403168: length 1.9
  TOP w0.381: OVRA/TRIGRDY.1 R58.1
N17405429: length 1.8
  TOP w0.381: OVRB/TRIGGER.1 R57.1
N17407540: length 26.4
  TOP w0.305: U12.44 65.72,76.59 66.53,77.39
  TOP w0.381: R53.1 79.61,87.88 76.65,84.92 67.84,84.92 66.78,83.86 66.78,77.65 66.53,77.39 ; R53.1 Q2.1 ; R53.1 R56.2
N17407548: length 22.8
  TOP w0.305: 67.54,77.52 66.22,76.2 U12.43
  TOP w0.381: R54.1 Q3.1 ; R54.1 68.69,83.19 67.54,82.04 67.54,77.52 ; R54.1 R55.2
N17461045: length 6
  TOP w0.203: STATUS_LD2.1 89.84,52.15 88.39,50.69 88.39,49.25 88.02,48.88 U13.48
N17467440: length 6.1
  TOP w0.33: C158.1 v1(90.49,46.23) ; C159.2 v1(90.49,41.74)
  BOTTOM w0.33: v1(90.49,46.23) v1(90.49,43.24) v1(90.49,41.74)
N17467450: length 1.8
  TOP w0.203: C153.1 89.29,46.41 88.14,46.41 88.09,46.36 U13.43
N17467802: length 1.8
  TOP w0.203: U13.35 88.09,42.37 88.14,42.32 89.29,42.32 C156.1
N17467807: length 1.8
  TOP w0.203: C157.1 89.29,41.92 88.14,41.92 88.09,41.87 U13.34
N17467978: length 1.8
  TOP w0.203: U13.38 88.09,43.87 88.14,43.82 89.29,43.82 C154.1
N17467983: length 1.8
  TOP w0.203: C155.1 89.29,43.42 88.14,43.42 88.09,43.36 U13.37
N17471425: length 19.1
  TOP w0.203: U13.31 86.66,40.37 86.29,40.01 86.29,35.99 87.76,34.52 87.76,24.07 STATUS_LD1.1
N17477944: length 12.2
  TOP w0.203: CLKIN_SEL1.1 75.37,50.93 79.66,50.93 80.46,50.13 81.91,50.13 82.16,49.88 U13.59
N17492975: length 15.2
  TOP w0.203: R94.2 v2(74.48,35.92) ; U13.5 78.49,46.87 v2(78.38,46.97)
  BOTTOM w0.203: R95.2 v2(74.48,35.92) 74.48,37.62 77.2,40.34 77.2,45.92 78.24,46.97 v2(78.38,46.97)
N17497915: length 7.5
  TOP w0.203: LMK_RESET.2 69.09,29.95 69.52,30.38 70.79,30.38 R94.1
N17498425: length 5.4
  TOP w0.203: R97.1 LMK_SYNC.2
N17498929: length 9.4
  TOP w0.381: Q4.1 R67.1 113.88,59.92 v1(114.53,60.58)
  BOTTOM w0.381: FMC.H31 v1(114.53,60.58)
N17500015: length 0.9
  BOTTOM w0.381: FMC.D31 v1(119.61,60.58)
N17500071: length 0.9
  BOTTOM w0.381: FMC.D30 v1(119.61,61.85)
N17502672: length 2.6
  TOP w0.254: U10.8 R168.2 R169.1
N17525558: length 11.6
  TOP w0.203: U13.58 82.64,50 81.97,50.67 80.7,50.67 79.91,51.46 CLKIN_SEL0.1
N17567551: length 17
  TOP w0.203: v2(52.85,54.3) 51.82,53.26 SYSREF_SW.2
  TOP w0.381: R51.2 v1(62.35,63.86)
  BOTTOM w0.203: v2(52.85,54.3) 52.85,56.33 R52.1 C113.2 v1(62.35,63.86)
N17588026: length 13.1
  BOTTOM w0.203: L1.1 R36.2 25.73,65.36 22.3,65.36 17.66,69.99 16.94,69.99 16.89,69.94 U3.24
N17588195: length 1.9
  BOTTOM w0.203: C21.2 13.3,61.08 12.47,60.26 T9.3
N17588197: length 1.9
  BOTTOM w0.203: T9.1 15.01,60.26 14.19,61.08 C20.2
N17588243: length 1.7
  BOTTOM w0.254: R34.2 18.15,70.94 U3.22
N17588312: length 3.4
  BOTTOM w0.254: v1(8.53,71.21) 8.76,71.44 U3.4
N17588326: length 3.4
  BOTTOM w0.254: v1(8.53,72.18) 8.76,71.94 U3.5
N17588682: length 6.9
  BOTTOM w0.203: U3.30 13.49,69.04 13.54,68.99 13.54,62.79 13.3,62.55 C21.1
N17588716: length 6.9
  BOTTOM w0.203: U3.29 13.99,69.04 13.95,68.99 13.95,62.79 14.19,62.55 C20.1
N17588832: length 13.1
  BOTTOM w0.203: U3.23 16.89,70.44 16.94,70.4 17.83,70.4 22.46,65.76 25.73,65.76 R37.2 L2.1
N17588912: length 13.1
  BOTTOM w0.203: L4.2 R38.2 25.73,77.62 22.46,77.62 17.83,72.99 16.94,72.99 16.89,72.94 U3.18
N17589096: length 6.9
  BOTTOM w0.203: C22.1 13.3,80.84 13.54,80.6 13.54,74.39 13.49,74.35 U3.11
N17589248: length 6.9
  BOTTOM w0.203: U3.12 13.99,74.35 13.95,74.39 13.95,80.6 14.19,80.84 C23.1
N17589348: length 1.7
  BOTTOM w0.254: U3.19 18.15,72.44 R35.2
N17589483: length 1.9
  BOTTOM w0.203: T8.3 15.01,83.13 14.19,82.31 C23.2
N17591143: length 13.1
  BOTTOM w0.203: U3.17 16.89,73.44 16.94,73.4 17.66,73.4 22.3,78.03 25.73,78.03 R39.2 L3.2
N17597838: length 8.9
  TOP w0.381: v2(29.95,9.91) 30.26,10.21 Z1.3 29.36,11.13 28.55,11.94 28.55,15.24 28.17,15.62 R120.2
  BOTTOM w0.381: R119.1 29.55,9.5 v2(29.95,9.91)
N17597840: length 6
  BOTTOM w0.381: U6.20 33.84,10.89 v2(33.87,10.86) 33.87,10.5 C183.1 34.02,9.91 33.76,9.65 31.58,9.65 R119.2
N17597844: length 11.3
  TOP w0.254: 28.17,9.03 U7.4 ; 28.3,10.35 U7.6
  TOP w0.508: 28.17,9.03 28.3,9.16 28.3,10.92 27.67,11.56 R120.1 25.63,14.35 25.13,14.85 C180.1
N17597872: length 7.4
  TOP w0.508: U7.1 24.3,10.35 23.98,10.03 23.98,8.26 23.52,7.79 C181.1
  TOP w1.27: Z3.1 C181.1
N17597980: length 1.9
  BOTTOM w0.203: U6.1 28.64,20.03 28.5,20.17 28.5,20.76 R126.1
N17597982: length 1.9
  BOTTOM w0.203: U6.5 31.24,20.74 R127.1
N17597984: length 1.8
  BOTTOM w0.203: R128.1 29.94,20.86 U6.3
N17597986: length 1.9
  BOTTOM w0.203: U6.11 35.14,20.91 R129.1
N17597988: length 1.9
  BOTTOM w0.203: R130.1 29.29,20.74 U6.2
N17597998: length 1.9
  BOTTOM w0.203: U6.9 33.84,20.74 R131.1
N17598000: length 1.8
  BOTTOM w0.203: R132.1 34.49,20.86 U6.10
N17598002: length 1.9
  BOTTOM w0.254: U6.6 31.89,20.28 32.05,20.45 32.05,20.8 R133.1
N17599264: length 4.7
  TOP w0.203: C185.1 36.38,10.9 v2(36.41,10.86) 36.37,10.81 USB.2
  BOTTOM w0.203: v2(36.41,10.86) 36.44,10.89 U6.16
N17599267: length 4.7
  TOP w0.203: USB.3 37.17,10.81 v2(37.12,10.86) 37.15,10.9 C186.1
  BOTTOM w0.203: U6.15 37.09,10.89 v2(37.12,10.86)
N17600241: length 2.8
  TOP w0.381: v2(35.03,7.15) 35.57,7.15 USB.1 35.57,8.89 v2(35.03,8.89)
  vias: v2(29.76,16.4) v2(29.82,15.49) v2(30.71,16.38) v2(30.71,15.49)
N17600317: length 1.9
  TOP w0.381: v2(35.82,13.53) 35.82,13.9 C187.1
  BOTTOM w0.381: v2(35.82,13.53) 35.79,13.5 U6.17
N17600450: length 1.9
  BOTTOM w0.203: U6.12 35.79,20.8 R121.1
N17601684: length 81.3
  L4_POWER w0.203: v2(49.51,65.23) 45.06,69.67 v2(45.06,93.47)
  BOTTOM w0.203: v2(45.06,93.47) R134.1 ; v2(49.51,65.23) 51.03,63.7 51.03,54.5 53.01,52.53 53.01,29.16 53.34,28.83 U14.3
N17602039: length 1.4
  BOTTOM w0.203: R138.1 21.13,38.38 U15.3
N17602344: length 1.4
  BOTTOM w0.203: U16.3 55.12,22.38 R141.1
N17602346: length 1.3
  BOTTOM w0.203: U16.4 R142.1
N17602348: length 1.4
  BOTTOM w0.203: R143.1 55.12,21.08 U16.5
N17602350: length 1.6
  BOTTOM w0.203: U16.6 54.8,20.43 55.24,19.99 R144.1
N17603643: length 82
  L4_POWER w0.203: v2(44.18,91.95) 44.18,69.04 v2(48.75,64.47)
  BOTTOM w0.203: U14.4 52.69,28.18 52.1,28.78 52.1,51.64 49.76,53.97 49.76,63.45 v2(48.75,64.47) ; v2(44.18,91.95) R135.1
N17603676: length 82.8
  L4_POWER w0.203: v2(43.29,90.42) 43.29,68.4 v2(47.99,63.7)
  BOTTOM w0.203: v2(43.29,90.42) R136.1 ; U14.5 52.04,27.53 51.18,28.4 51.18,50.75 48.49,53.44 48.49,63.2 v2(47.99,63.7)
N17603709: length 83.5
  L4_POWER w0.203: v2(47.22,62.94) 42.4,67.77 v2(42.4,88.9)
  BOTTOM w0.203: v2(47.22,62.94) 47.22,52.9 50.27,49.86 50.27,28.02 51.4,26.88 U14.6 ; v2(42.4,88.9) R137.1
N17603775: length 1.3
  BOTTOM w0.203: U15.4 R139.1
N17603808: length 1.4
  BOTTOM w0.203: U15.5 22.43,38.38 R140.1
N17607444: length 3.2
  BOTTOM w0.203: JP2.2 48.74,17.2 R159.1 U16.9
N17608737: length 26.5
  L4_POWER w0.203: v2(12.79,68.24) 12.79,66.58 24.13,55.24 24.13,53.44 J1.4
  BOTTOM w0.203: R17.2 J1.4
  BOTTOM w0.254: v2(12.79,68.24) 12.99,68.44 U3.31
N17692169: length 5.8
  TOP w0.203: C2.2 20.42,84.88 22.72,84.88 23.79,83.81 T2.4
N17692215: length 13.9
  TOP w0.33: T1.4 13.63,83.67 R2.1 11.31,83.67 6.5,78.86 VINA-.1
N17692227: length 1.3
  TOP w0.203: C1.1 T1.1
N17692229: length 1.3
  TOP w0.203: T1.3 C2.1
N17692231: length 13.9
  TOP w0.33: VINA+.1 6.5,91.3 11.31,86.49 R1.2 13.63,86.49 T1.6
N17692255: length 13.9
  TOP w0.33: T7.4 13.63,56.9 R5.2 11.31,56.9 6.5,52.09 VINB+.1
N17692293: length 5.8
  TOP w0.203: T6.4 23.79,57.04 22.72,58.11 20.42,58.11 C5.2
N17692319: length 1.3
  TOP w0.203: C6.1 T7.2
N17692331: length 5.8
  TOP w0.203: T6.6 23.79,59.58 22.72,58.51 20.42,58.51 C4.2
N17692399: length 5.8
  TOP w0.203: C1.2 20.42,85.28 22.72,85.28 23.79,86.35 T2.6
N17692405: length 30
  TOP w0.33: R10.2 52.22,74.71 v1(52.2,74.69) 52.2,74.02 R11.2
  BOTTOM w0.203: VCMA.1 C9.1
  BOTTOM w0.406: v1(52.2,74.69) 49.92,76.96 49.2,76.96 43.71,82.45 35.51,82.45 C9.1 R7.2
N17692416: length 7.6
  TOP w0.203: R12.2 56.88,73.38 55.85,73.38 54.36,74.88 53.75,74.88 R10.1 52.68,75.95 51.39,75.95 v1(50.7,75.26)
N17692426: length 5.6
  TOP w0.381: T2.2 v1(28.96,85.08)
  BOTTOM w0.203: 29.47,85.6 30.18,85.6 30.63,85.14 R7.1 30.63,85.02 30.18,84.56 29.47,84.56 v1(28.96,85.08) 29.47,85.6
N17692454: length 13.9
  TOP w0.33: T7.6 13.63,59.72 R4.2 11.31,59.72 6.5,64.53 VINB-.1
N17692538: length 30
  TOP w0.33: R23.2 52.19,68.69 v1(52.2,68.69) R22.2
  BOTTOM w0.203: C11.1 VCMB.1
  BOTTOM w0.406: v1(52.2,68.69) 49.88,66.37 49.15,66.37 43.72,60.94 35.51,60.94 C11.1 R26.2
N17692596: length 1.3
  TOP w0.203: T7.3 C5.1
N17692598: length 1.3
  TOP w0.203: C4.1 T7.1
N17692610: length 7.6
  TOP w0.203: v1(50.72,74.02) 51.33,73.41 52.61,73.41 R11.1 53.67,74.47 54.19,74.47 55.61,73.05 56.86,73.05 R13.2
N17692612: length 5.6
  TOP w0.381: v1(28.96,58.31) T6.2
  BOTTOM w0.203: 30.18,57.79 29.47,57.79 v1(28.96,58.31) 29.47,58.83 30.18,58.83 30.63,58.37 R26.1 30.63,58.25 30.18,57.79
N17692676: length 1.3
  TOP w0.203: C3.1 T1.2
N17695733: length 1
  BOTTOM w0.203: C40.1 31.47,64.24 L6.1
N17695767: length 1
  BOTTOM w0.203: L7.1 31.47,66.88 C41.1
N17701277: length 1.9
  BOTTOM w0.203: T8.1 12.47,83.13 13.3,82.31 C22.2
N17703127: length 7.9
  TOP w0.203: v1(50.7,69.34) 51.34,69.98 52.63,69.98 R22.1 53.75,68.86 54.31,68.86 55.78,70.33 57.09,70.33 R24.2
N17703165: length 7.9
  TOP w0.203: v1(50.7,68.07) 51.36,67.41 52.52,67.41 52.53,67.41 52.66,67.41 R23.1 53.7,68.45 54.48,68.45 56.03,70 57.14,70 R25.2
N17704949: length 1
  BOTTOM w0.203: C46.1 31.47,76.51 L10.1
N17704975: length 1
  BOTTOM w0.203: L11.1 31.47,79.15 C47.1
N17708763: length 13.5
  TOP w0.203: T3.3 60.53,40.66 59.48,41.71 59.48,47.57 61.17,49.27 61.17,52.15 R73.1
N17708767: length 13.5
  TOP w0.203: R72.1 60.77,52.15 60.77,49.44 59.07,47.74 59.07,41.76 57.99,40.68 T3.1
N17709160: length 15.7
  TOP w0.203: T4.1 66.51,40.86 67.51,41.86 67.51,44.58 63.75,48.34 63.75,53.56 R78.1
N17709162: length 15.8
  TOP w0.203: R79.1 64.16,53.53 64.16,48.5 67.92,44.75 67.92,41.86 69.05,40.73 T4.3
N17709444: length 5.9
  TOP w0.33: CLK.1 50.77,1.89 R70.1 50.77,7.62 R220.1
N17709615: length 36.5
  TOP w0.33: T4.6 R71.1 66.51,35.35 65.43,34.26 65.43,7.92 62.7,5.19 SYSREF.1
N17746469: length 1.1
  BOTTOM w0.203: R36.1 27.08,65.13 27.08,64.24 C28.2
N17746475: length 1.1
  BOTTOM w0.203: C29.2 27.08,66.88 27.08,65.99 R37.1
N17746481: length 1.1
  BOTTOM w0.203: R38.1 27.08,77.4 27.08,76.51 C30.2
N17746487: length 1.1
  BOTTOM w0.203: C31.2 27.08,79.15 27.08,78.26 R39.1
N17748434: length 7.6
  BOTTOM w0.559: 7.62,37.11 v2(7.27,37.11) v2(7.27,36.09) v2(7.97,36.09) v2(7.97,37.11) 7.62,37.11 ; 7.62,37.11 7.62,36.6
  BOTTOM w0.762: 7.62,36.6 R181.2
  BOTTOM w1.27: UNK+5V.1 Z17.1
N17896945: length 1.8
  BOTTOM w0.203: R145.1 72.49,16.33 LMKSPI.6
N17897426: length 1.6
  BOTTOM w0.203: LMKSPI.9 R40.2
N17899231: length 4.8
  BOTTOM w0.203: LMKSPI.7 74.27,14.55 R152.1
N17899957: length 4.9
  BOTTOM w0.203: LMKSPI.1 69.19,14.55 69.19,17.27 R156.1
N17947980: length 12.4
  BOTTOM w0.254: v1(46.91,30.12) 48.15,30.12 U14.16
  BOTTOM w0.33: JP1.2 43.31,29.26 43.31,30.56 43.89,31.14 45.58,31.14 C195.2 46.63,30.4 v1(46.91,30.12)
N18004813: length 1.8
  TOP w0.33: R219.2 R217.2 51.94,9.27 R221.2
N18004844: length 31.1
  TOP w0.33: R220.2 R221.1 50.85,9.4 50.85,11.02 57.99,18.16 T3.6
N18006132: length 3.4
  TOP w0.203: T3.2 v1(59.26,36.77)
N18006814: length 3.4
  TOP w0.203: T4.2 v1(67.78,36.77)
N172049681: length 1.3
  TOP w0.33: C161.2 R104.1
N173478561: length 1.9
  TOP w0.381: Q2.3 OVRA/TRIGRDY.2
N173944760: length 1.9
  TOP w0.381: SYNC.1 R68.2
N174054101: length 1.9
  TOP w0.381: OVRB/TRIGGER.2 Q3.3

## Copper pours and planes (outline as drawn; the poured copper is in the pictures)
+4V on L3_POWER: 98.43,0.64 98.43,6.05 44.84,6.05 44.84,23.84 0.64,23.84 0.64,34.29 24.59,34.29 24.59,77.65 6.12,77.65 6.12,97.64 0.64,97.64 0.64,106.68 104.22,106.68 104.22,81.76 132.19,81.76 132.19,39.88 107.55,39.88 107.55,0.64 ; 7 cut-outs
GND on TOP: 44.85,0.05 44.85,23.84 0.64,23.84 0.64,46.38 0.05,46.38 0.05,97.01 0.64,97.01 0.64,106.68 132.19,106.68 132.19,39.88 107.55,39.88 107.55,0.64 97.8,0.64 97.8,0.05 ; 5 cut-outs
GND on BOTTOM: 44.85,0.05 44.85,23.84 0.64,23.84 0.64,46.38 0.05,46.38 0.05,97.01 0.64,97.01 0.64,106.68 132.19,106.68 132.19,39.88 107.55,39.88 107.55,0.64 97.8,0.64 97.8,0.05 ; 2 cut-outs
GND on L2_GND: 44.85,0.05 44.85,23.84 0.64,23.84 0.64,46.38 0.05,46.38 0.05,97.01 0.64,97.01 0.64,106.68 132.19,106.68 132.19,39.88 107.55,39.88 107.55,0.64 97.8,0.64 97.8,0.05 ; 1 cut-out
GND on L3_POWER: 97.8,0.05 44.85,0.05 44.85,5.41 97.8,5.41
GND on L3_POWER: 0.05,46.38 0.05,97.01 5.49,97.01 5.49,46.38
GND on L3_POWER: 104.86,106.68 104.86,82.58 132.19,82.58 132.19,106.68
GND on L4_POWER: 44.85,0.05 44.85,23.84 0.64,23.84 0.64,46.38 0.05,46.38 0.05,97.01 0.64,97.01 0.64,106.68 132.19,106.68 132.19,39.88 107.55,39.88 107.55,0.64 97.8,0.64 97.8,0.05 ; 3 cut-outs
GND on L5_GND: 44.85,0.05 44.85,23.84 0.64,23.84 0.64,46.38 0.05,46.38 0.05,97.01 0.64,97.01 0.64,106.68 132.19,106.68 132.19,39.88 107.55,39.88 107.55,0.64 97.8,0.64 97.8,0.05 ; 5 cut-outs
GND2 on TOP, L2_GND, L4_POWER, L5_GND: 0.64,0.64 0.64,23.2 44.21,23.2 44.21,0.64
GND2 on BOTTOM: 0.64,0.64 0.64,23.2 44.21,23.2 44.21,0.64 ; 1 cut-out
LMK_VCC1/5/6 on L3_POWER: 78.08,45.97 78.08,41.05 88.68,41.05 88.68,45.97
VA3.0 on L3_POWER: 30.08,39.24 30.08,43.56 35.29,43.56 35.29,50.55 49.89,50.55 49.89,43.03 46.1,39.24
VAMP on L3_POWER: 6.12,48.72 6.12,77.02 23.95,77.02 23.95,48.72
VLMK3.3 on L3_POWER: 66.65,52.12 66.65,15.24 90.45,15.24 90.45,52.12 ; 1 cut-out
VSPI1.8 on L3_POWER: 0.64,0.64 0.64,23.2 44.21,23.2 44.21,12.48 40.75,12.48 40.75,17.56 23.49,17.56 23.49,0.64
N17600241 on L3_POWER: 24.12,0.64 24.12,16.93 40.11,16.93 40.11,11.85 44.21,11.85 44.21,0.64
N17748434 on L3_POWER: 0.64,45.75 0.64,34.92 23.95,34.92 23.95,48.09 6.12,48.09 6.12,45.75

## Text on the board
BOTTOM: UL94V-0 | MADE IN U.S.A | LAYER 6- BOTTOM SIDE
Board Geometry/Soldermask Bottom: SOLDERMASK BOTTOM
Package Geometry/Pastemask Bottom: PASTEMASK BOTTOM
Ref Des/Silkscreen Bottom: SILKSCREEN BOTTOM | +
User.Comments: 1 | T8 | T9 | FMC | C232 | C162 | Y1 | C163 | C174 | C168 | R112 | Y3 | Y2 | C132 | C133 | C139 | C137 | L27 | C136 | C138 | C140 | R162 | R96 | R40 | C201 | C130 | C149 | C131 | C147 | C135 | C134 | R98 | C97 | R65 | R66 | R63 | R64 | C95 | C121 | C98 | C120 | C70 | C72 | C75 | C76 | C78 | R141 | R142 | R143 | C115 | C113 | C118 | R52 | R134 | R135 | R136 | R137 | C116 | C119 | R27 | R16 | U14 | U16 | C193 | R15 | R14 | R28 | R29 | R159 | C195 | C190 | C227 | C225 | C216 | C45 | C44 | C51 | C50 | C183 | C9 | C11 | L11 | L10 | L7 | L6 | U6 | R26 | C14 | C13 | C16 | C15 | C41 | C40 | C46 | R119 | C47 | R7 | C29 | C28 | C30 | C31 | L3 | L4 | L2 | L1 | R37 | R36 | R38 | R39 | R17 | U15 | R35 | R34 | C25 | C24 | C26 | C27 | C192 | U3 | Z17 | Z2 | C239 | C237 | L22 | L23 | R103 | L21 | C235 | L26 | C144 | C143 | C142 | L25 | L20 | C141 | C145 | L24 | L28 | R150 | R151 | R95 | R152 | R153 | R145 | R148 | R149 | R155 | R156 | C91 | R147 | C89 | R146 | R80 | C86 | C60 | R81 | C87 | R82 | C171 | R83 | C170 | C84 | C63 | R77 | C173 | C81 | R76 | C172 | C79 | R75 | R74 | R144 | R125 | C194 | R121 | R129 | R132 | R131 | C49 | C43 | R133 | L12 | L8 | R127 | C184 | R128 | C48 | C42 | R130 | L9 | L5 | R126 | R140 | R139 | R138 | C191 | C23 | C20 | C22 | C21 | C242 | R33 | R30 | C241 | R181 | TEXAS INSTRUMENTS, INC. | ADC16DX370/LM97937 EVM | PCB REV A
TOP: c  2014 TEXAS INSTRUMENTS | LAYER 1- TOP SIDE
Board Geometry/Soldermask Top: SOLDERMASK TOP
Package Geometry/Pastemask Top: PASTEMASK TOP
Ref Des/Silkscreen Top: 1.8V SDO | 3.0V SDO | S/N | ADC16DX370EVM | LM97937EVM | PCB REV A | GND | + | SILKSCREEN TOP
L2_GND: LAYER 2- GROUND PLANE 1
L3_POWER: LAYER 3- POWER PLANE
L4_POWER: LAYER 4- GROUND PLANE 2
L5_GND: LAYER 5- GROUND PLANE 3
User.35: 40 | 1 | INIT | DONE | K | J | H | G | F | E | D | C | B | A | 76 | VCCAUX_IO | 20 | 15 | 2 | 19 | 11 | PMBus | 3 | 4 | 2-3: LOW BW RX | 10 | GPIO LEDS | MH6 | J2 | SFP | P5 | J8 | MH9 | SW4 | MH1 | MH5 | U65 | XADC HDR | J46 | C780
User.41: TOTAL THICKNESS 0.0625" +/- 0.004" | STACK-UP: | Bottom side solder mask+silkscreen | Top side solder mask+silkscreen | LAYER 4 | LAYER 2 | LAYER 3 | LAYER 5 | LAYER 6 | LAYER 1 | NP 4000-6 | ROGERS R04350 | 0.0046 | 0.0066 | 1 OZ.COPPER | 1 OZ.COPPER PLATED UP TO 2 OZ
User.45: FIGURE | SIZE | 8.0 | 12.0 | 36.0 | 37.0 | 38.0 | 56.0 | 63.0 | 116.0 | 125.0 | 46.0 | 51.0 | 59.84 | DRILL CHART: TOP to BOTTOM | ALL UNITS ARE IN MILS | PLATED | NON-PLATED | QTY | 46 | 2458 | 17 | 2 | 22 | 3 | 4 | 23 | 1
